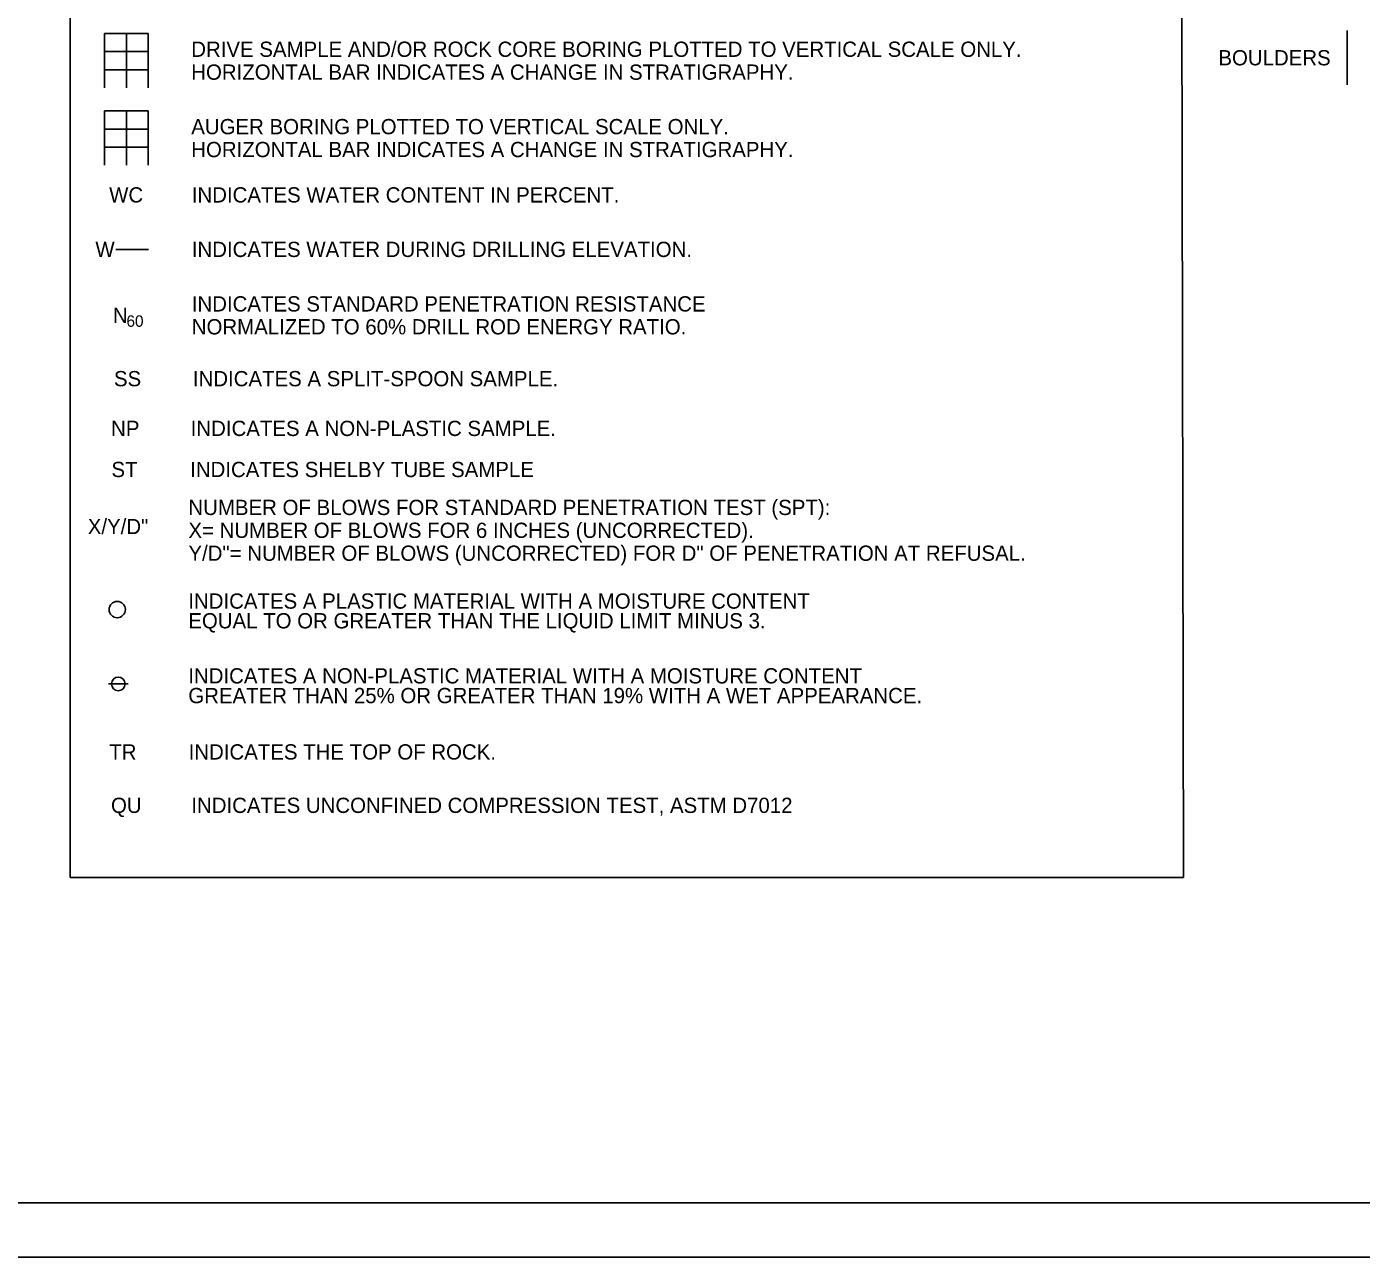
# Model space of a CAD drawing. Extents: x -5.4 to 49.9, y 13.2 to 48.4.
# Drawn here: x 14.02 to 26.26, y 26.43 to 37.72 of the extents above; entities that cross this region are included whole.
import ezdxf

# ---------------------------------------------------------------- set-up
doc = ezdxf.new("R2010")
doc.units = 0
for name, color, linetype in [('GT_Project_Cells', 7, 'Continuous'), ('GT_Project_Soil_Boring', 7, 'Continuous'), ('SH_Border', 7, 'Continuous'), ('SH_Cut_Line', 7, 'Continuous'), ('SH_Data', 7, 'Continuous'), ('SH_Text', 7, 'Continuous')]:
    doc.layers.add(name, color=color, linetype=linetype)

msp = doc.modelspace()

# ---------------------------------------------------------------- linework, layer by layer
at = {"layer": 'GT_Project_Cells'}
msp.add_line((14.833, 35.675), (15.133, 35.675), dxfattribs=at)
at = {"layer": 'GT_Project_Soil_Boring'}
for p, q in [((14.731, 37.656), (15.131, 37.656)), ((14.731, 37.656), (14.731, 37.156)), ((14.931, 37.656), (14.931, 37.156)), ((15.131, 37.656), (15.131, 37.156)), ((14.731, 37.489), (15.131, 37.489)), ((14.731, 37.322), (15.131, 37.322)), ((14.731, 36.946), (15.131, 36.946)), ((14.731, 36.946), (14.731, 36.446)), ((14.931, 36.946), (14.931, 36.446)), ((15.131, 36.946), (15.131, 36.446)), ((14.731, 36.779), (15.131, 36.779)), ((14.731, 36.612), (15.131, 36.612))]:
    msp.add_line(p, q, dxfattribs=at)
at = {"layer": 'SH_Border'}
msp.add_lwpolyline([(4.289, 47.929), (36.289, 47.929), (36.289, 26.929), (4.289, 26.929)], close=True, dxfattribs=at)
at = {"layer": 'SH_Cut_Line'}
msp.add_line((14.767, 31.689), (14.947, 31.689), dxfattribs=at)
msp.add_lwpolyline([(2.789, 26.429), (36.789, 26.429), (36.789, 48.429), (2.789, 48.429)], close=True, dxfattribs=at)
for centre, radius in [((14.847, 32.371), 0.0748), ((14.857, 31.689), 0.0625)]:
    msp.add_circle(centre, radius, dxfattribs=at)
at = {"layer": 'SH_Data'}
for p, q in [((14.415, 29.912), (14.415, 47.848)), ((24.626, 29.912), (24.59, 47.848)), ((24.626, 29.912), (14.415, 29.912))]:
    msp.add_line(p, q, dxfattribs=at)
at = {"layer": 'SH_Text'}
msp.add_line((26.126, 37.183), (26.126, 37.683), dxfattribs=at)

# ---------------------------------------------------------------- texts
at = {"layer": 'GT_Project_Cells'}
msp.add_text('W', height=0.14, dxfattribs=at).set_placement((14.647, 35.605))
at = {"layer": 'SH_Text'}
for s, height, p in [('DRIVE SAMPLE AND/OR ROCK CORE BORING PLOTTED TO VERTICAL SCALE ONLY.', 0.14, (15.526, 37.441)), ('BOULDERS', 0.14, (24.946, 37.363)), ('HORIZONTAL BAR INDICATES A CHANGE IN STRATIGRAPHY.', 0.14, (15.526, 37.231)), ('AUGER BORING PLOTTED TO VERTICAL SCALE ONLY.', 0.14, (15.526, 36.731)), ('HORIZONTAL BAR INDICATES A CHANGE IN STRATIGRAPHY.', 0.14, (15.526, 36.521)), ('WC', 0.14, (14.773, 36.105)), ('INDICATES WATER CONTENT IN PERCENT.', 0.14, (15.531, 36.105)), ('INDICATES WATER DURING DRILLING ELEVATION.', 0.14, (15.531, 35.605)), ('N', 0.14, (14.807, 35)), ('INDICATES STANDARD PENETRATION RESISTANCE', 0.14, (15.531, 35.105)), ('60', 0.105, (14.932, 34.965)), ('NORMALIZED TO 60% DRILL ROD ENERGY RATIO.', 0.14, (15.531, 34.895)), ('SS', 0.14, (14.817, 34.419)), ('INDICATES A SPLIT-SPOON SAMPLE.', 0.14, (15.541, 34.419)), ('NP', 0.14, (14.791, 33.963)), ('INDICATES A NON-PLASTIC SAMPLE.', 0.14, (15.521, 33.963)), ('ST', 0.14, (14.794, 33.586)), ('INDICATES SHELBY TUBE SAMPLE', 0.14, (15.516, 33.586)), ('NUMBER OF BLOWS FOR STANDARD PENETRATION TEST (SPT):', 0.14, (15.5, 33.238)), ('X/Y/D"', 0.14, (14.577, 33.063)), ('X= NUMBER OF BLOWS FOR 6 INCHES (UNCORRECTED).', 0.14, (15.5, 33.028)), ('Y/D"= NUMBER OF BLOWS (UNCORRECTED) FOR D" OF PENETRATION AT REFUSAL.', 0.14, (15.5, 32.818)), ('INDICATES A PLASTIC MATERIAL WITH A MOISTURE CONTENT ', 0.14, (15.499, 32.379)), ('EQUAL TO OR GREATER THAN THE LIQUID LIMIT MINUS 3.', 0.14, (15.499, 32.198)), ('INDICATES A NON-PLASTIC MATERIAL WITH A MOISTURE CONTENT', 0.14, (15.499, 31.693)), ('GREATER THAN 25% OR GREATER THAN 19% WITH A WET APPEARANCE.', 0.14, (15.499, 31.512)), ('TR', 0.14, (14.774, 30.995)), ('INDICATES THE TOP OF ROCK.', 0.14, (15.502, 30.995)), ('QU', 0.14, (14.79, 30.505)), ('INDICATES UNCONFINED COMPRESSION TEST, ASTM D7012', 0.14, (15.527, 30.505))]:
    msp.add_text(s, height=height, dxfattribs=at).set_placement(p)

doc.saveas('drawing.dxf')
